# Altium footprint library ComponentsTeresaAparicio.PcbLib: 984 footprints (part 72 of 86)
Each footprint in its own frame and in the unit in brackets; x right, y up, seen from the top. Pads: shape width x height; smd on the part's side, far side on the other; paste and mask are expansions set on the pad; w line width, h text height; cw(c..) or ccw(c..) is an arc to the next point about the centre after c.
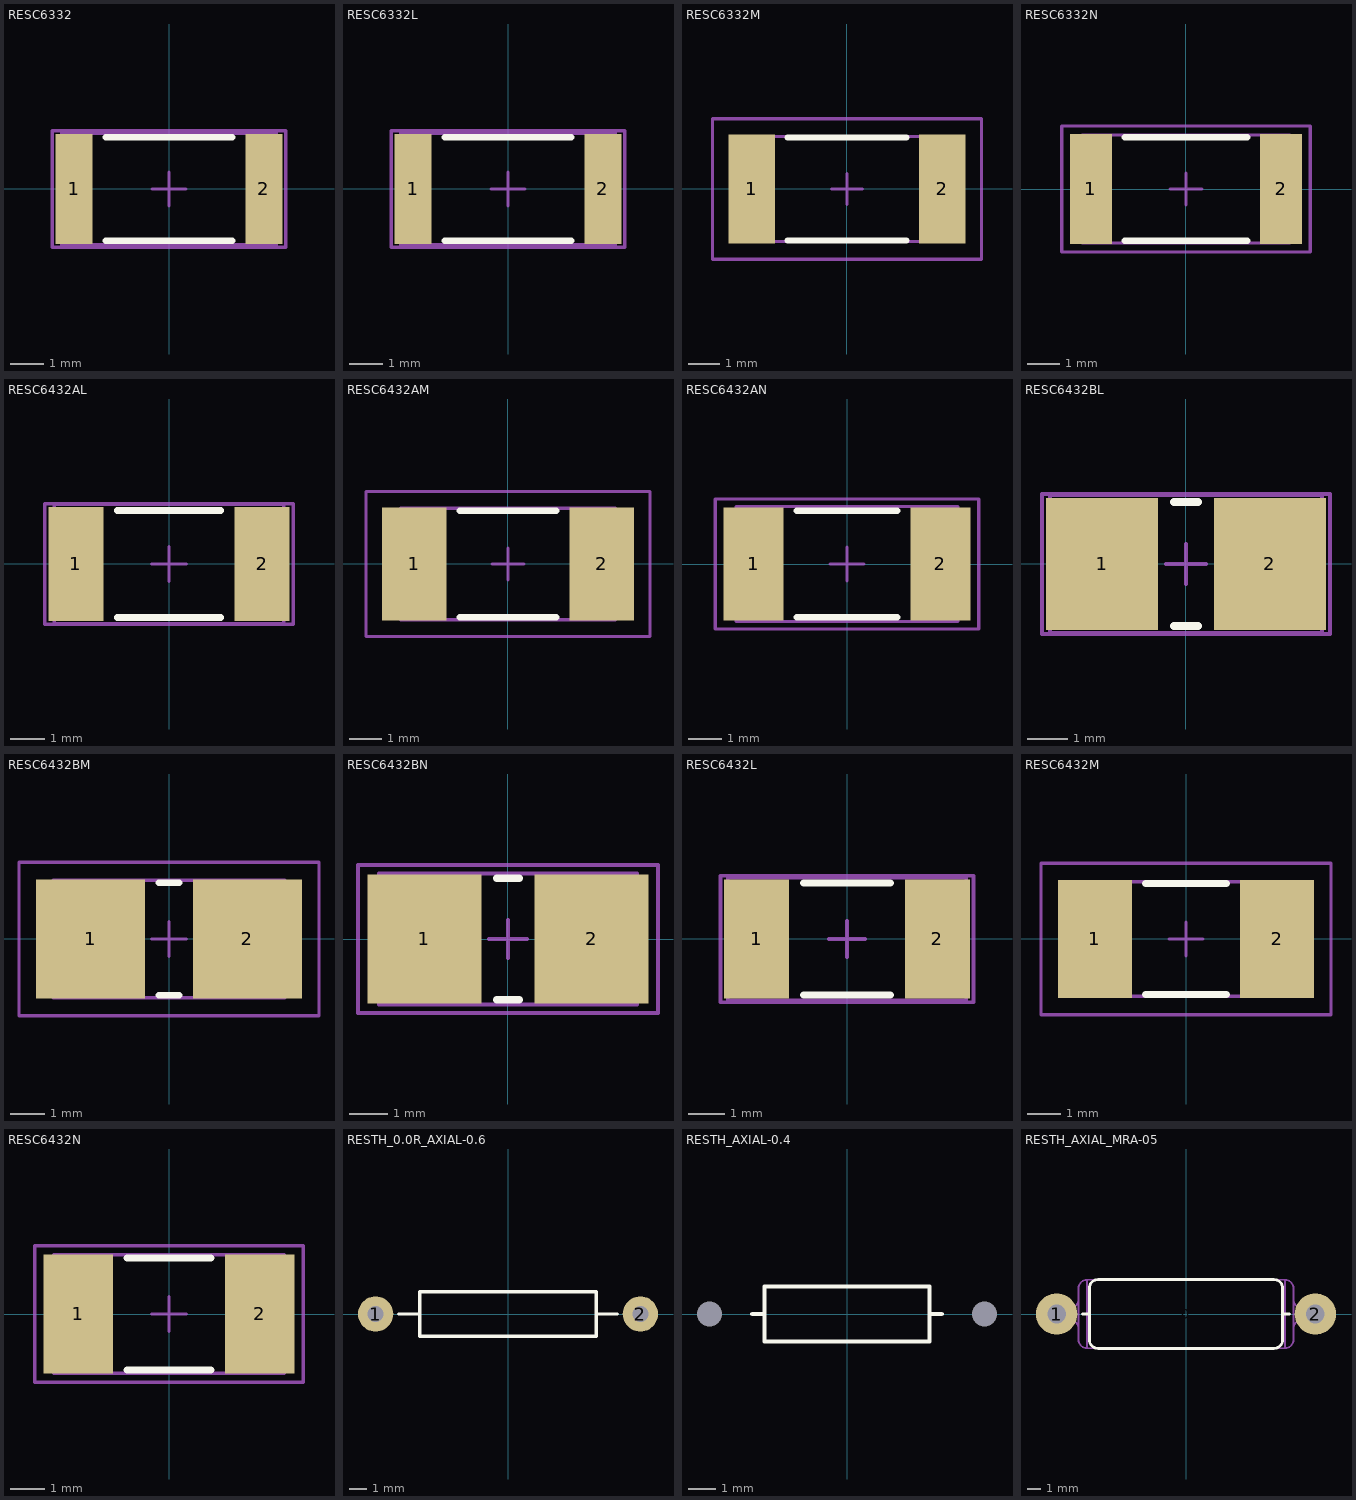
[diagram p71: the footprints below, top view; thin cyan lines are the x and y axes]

## RESC6332 [mm] "Chip Resistor, Body 6.3x3.2mm, IPC High Density"
height 0.9
pads (2):
  rect 1.1x3.3 smd: 1(-2.85,0) 2(2.85,0)
Top Overlay:
  lines w0.2: -1.9,-1.55 1.9,-1.55 ; -1.9,1.55 1.9,1.55
Mechanical 13:
  lines w0.1: -3.225,-1.675 -3.225,1.675 3.225,1.675 3.225,-1.675 -3.225,-1.675
Mechanical 15:
  lines w0.1: -0.5,0 0.5,0 ; 0,-0.5 0,0.5 ; -3.5,-1.75 -3.5,1.75 3.5,1.75 3.5,-1.75 -3.5,-1.75
3D body: height 0.9, standoff 0, extent -3.225,-1.675 3.225,1.675

## RESC6332L [mm] "Chip Resistor, Body 6.3x3.2mm, IPC High Density"
height 0.71
pads (2):
  rect 1.1x3.3 smd: 1(-2.85,0) 2(2.85,0)
Top Overlay:
  lines w0.2: -1.9,-1.55 1.9,-1.55 ; -1.9,1.55 1.9,1.55
Mechanical 13:
  lines w0.1: -3.225,-1.675 3.225,-1.675 3.225,1.675 -3.225,1.675 -3.225,-1.675
Mechanical 15:
  lines w0.1: -0.5,0 0.5,0 ; 0,-0.5 0,0.5 ; -3.5,-1.75 3.5,-1.75 3.5,1.75 -3.5,1.75 -3.5,-1.75
3D body: height 0.71, standoff 0, extent -3.225,-1.675 3.225,1.675

## RESC6332M [mm] "Chip Resistor, Body 6.3x3.2mm, IPC Low Density"
height 0.71
pads (2):
  rect 1.5x3.5 smd: 1(-3.05,0) 2(3.05,0)
Top Overlay:
  lines w0.2: -1.9,-1.65 1.9,-1.65 ; -1.9,1.65 1.9,1.65
Mechanical 13:
  lines w0.1: -3.225,-1.675 -3.225,1.675 3.225,1.675 3.225,-1.675 -3.225,-1.675
Mechanical 15:
  lines w0.1: -0.5,0 0.5,0 ; 0,-0.5 0,0.5 ; -4.3,-2.25 -4.3,2.25 4.3,2.25 4.3,-2.25 -4.3,-2.25
3D body: height 0.71, standoff 0, extent -3.225,-1.675 3.225,1.675

## RESC6332N [mm] "Chip Resistor, Body 6.3x3.2mm, IPC Medium Density"
height 0.71
pads (2):
  rect 1.3x3.4 smd: 1(-2.95,0) 2(2.95,0)
Top Overlay:
  lines w0.2: -1.9,-1.6 1.9,-1.6 ; -1.9,1.6 1.9,1.6
Mechanical 13:
  lines w0.1: -3.225,-1.675 3.225,-1.675 3.225,1.675 -3.225,1.675 -3.225,-1.675
Mechanical 15:
  lines w0.1: -0.5,0 0.5,0 ; 0,-0.5 0,0.5 ; -3.85,-1.95 3.85,-1.95 3.85,1.95 -3.85,1.95 -3.85,-1.95
3D body: height 0.71, standoff 0, extent -3.225,-1.675 3.225,1.675

## RESC6432AL [mm] "Chip Resistor, Body 6.4x3.2mm, IPC High Density"
height 1.1
pads (2):
  rect 1.6x3.3 smd: 1(-2.7,0) 2(2.7,0)
Top Overlay:
  lines w0.2: -1.5,-1.55 1.5,-1.55 ; -1.5,1.55 1.5,1.55
Mechanical 13:
  lines w0.1: -3.325,-1.725 3.325,-1.725 3.325,1.725 -3.325,1.725 -3.325,-1.725
Mechanical 15:
  lines w0.1: -0.5,0 0.5,0 ; 0,-0.5 0,0.5 ; -3.6,-1.75 3.6,-1.75 3.6,1.75 -3.6,1.75 -3.6,-1.75
3D body: height 1.1, standoff 0, extent -3.325,-1.725 3.325,1.725

## RESC6432AM [mm] "Chip Resistor, Body 6.4x3.2mm, IPC Low Density"
height 1.1
pads (2):
  rect 2x3.5 smd: 1(-2.9,0) 2(2.9,0)
Top Overlay:
  lines w0.2: -1.5,-1.65 1.5,-1.65 ; -1.5,1.65 1.5,1.65
Mechanical 13:
  lines w0.1: -3.325,-1.725 -3.325,1.725 3.325,1.725 3.325,-1.725 -3.325,-1.725
Mechanical 15:
  lines w0.1: -0.5,0 0.5,0 ; 0,-0.5 0,0.5 ; -4.4,-2.25 -4.4,2.25 4.4,2.25 4.4,-2.25 -4.4,-2.25
3D body: height 1.1, standoff 0, extent -3.325,-1.725 3.325,1.725

## RESC6432AN [mm] "Chip Resistor, Body 6.4x3.2mm, IPC Medium Density"
height 1.1
pads (2):
  rect 1.8x3.4 smd: 1(-2.8,0) 2(2.8,0)
Top Overlay:
  lines w0.2: -1.5,-1.6 1.5,-1.6 ; -1.5,1.6 1.5,1.6
Mechanical 13:
  lines w0.1: -3.325,-1.725 3.325,-1.725 3.325,1.725 -3.325,1.725 -3.325,-1.725
Mechanical 15:
  lines w0.1: -0.5,0 0.5,0 ; 0,-0.5 0,0.5 ; -3.95,-1.95 3.95,-1.95 3.95,1.95 -3.95,1.95 -3.95,-1.95
3D body: height 1.1, standoff 0, extent -3.325,-1.725 3.325,1.725

## RESC6432BL [mm] "Chip Resistor, Body 6.4x3.2mm, IPC High Density"
height 1.1
pads (2):
  rect 2.8x3.3 smd: 1(-2.1,0) 2(2.1,0)
Top Overlay:
  lines w0.2: -0.3,-1.55 0.3,-1.55 ; -0.3,1.55 0.3,1.55
Mechanical 13:
  lines w0.1: -3.4,-1.725 3.4,-1.725 3.4,1.725 -3.4,1.725 -3.4,-1.725
Mechanical 15:
  lines w0.1: -0.5,0 0.5,0 ; 0,-0.5 0,0.5 ; -3.6,-1.75 3.6,-1.75 3.6,1.75 -3.6,1.75 -3.6,-1.75
3D body: height 1.1, standoff 0, extent -3.4,-1.725 3.4,1.725

## RESC6432BM [mm] "Chip Resistor, Body 6.4x3.2mm, IPC Low Density"
height 1.1
pads (2):
  rect 3.2x3.5 smd: 1(-2.3,0) 2(2.3,0)
Top Overlay:
  lines w0.2: -0.3,-1.65 0.3,-1.65 ; -0.3,1.65 0.3,1.65
Mechanical 13:
  lines w0.1: -3.4,-1.725 3.4,-1.725 3.4,1.725 -3.4,1.725 -3.4,-1.725
Mechanical 15:
  lines w0.1: -0.5,0 0.5,0 ; 0,-0.5 0,0.5 ; -4.4,-2.25 4.4,-2.25 4.4,2.25 -4.4,2.25 -4.4,-2.25
3D body: height 1.1, standoff 0, extent -3.4,-1.725 3.4,1.725

## RESC6432BN [mm] "Chip Resistor, Body 6.4x3.2mm, IPC Medium Density"
height 1.1
pads (2):
  rect 3x3.4 smd: 1(-2.2,0) 2(2.2,0)
Top Overlay:
  lines w0.2: -0.3,-1.6 0.3,-1.6 ; -0.3,1.6 0.3,1.6
Mechanical 13:
  lines w0.1: -3.4,-1.725 3.4,-1.725 3.4,1.725 -3.4,1.725 -3.4,-1.725
Mechanical 15:
  lines w0.1: -0.5,0 0.5,0 ; 0,-0.5 0,0.5 ; -3.95,-1.95 3.95,-1.95 3.95,1.95 -3.95,1.95 -3.95,-1.95
3D body: height 1.1, standoff 0, extent -3.4,-1.725 3.4,1.725

## RESC6432L [mm] "Chip Resistor, Body 6.4x3.2mm, IPC High Density"
height 1.2
pads (2):
  rect 1.8x3.3 smd: 1(-2.5,0) 2(2.5,0)
Top Overlay:
  lines w0.2: -1.2,-1.55 1.2,-1.55 ; -1.2,1.55 1.2,1.55
Mechanical 13:
  lines w0.1: -3.3,-1.7 3.3,-1.7 3.3,1.7 -3.3,1.7 -3.3,-1.7
Mechanical 15:
  lines w0.1: -0.5,0 0.5,0 ; 0,-0.5 0,0.5 ; -3.5,-1.75 3.5,-1.75 3.5,1.75 -3.5,1.75 -3.5,-1.75
3D body: height 1.2, standoff 0, extent -3.3,-1.7 3.3,1.7

## RESC6432M [mm] "Chip Resistor, Body 6.4x3.2mm, IPC Low Density"
height 1.2
pads (2):
  rect 2.2x3.5 smd: 1(-2.7,0) 2(2.7,0)
Top Overlay:
  lines w0.2: -1.2,-1.65 1.2,-1.65 ; -1.2,1.65 1.2,1.65
Mechanical 13:
  lines w0.1: -3.3,-1.7 -3.3,1.7 3.3,1.7 3.3,-1.7 -3.3,-1.7
Mechanical 15:
  lines w0.1: -0.5,0 0.5,0 ; 0,-0.5 0,0.5 ; -4.3,-2.25 -4.3,2.25 4.3,2.25 4.3,-2.25 -4.3,-2.25
3D body: height 1.2, standoff 0, extent -3.3,-1.7 3.3,1.7

## RESC6432N [mm] "Chip Resistor, Body 6.4x3.2mm, IPC Medium Density"
height 1.2
pads (2):
  rect 2x3.4 smd: 1(-2.6,0) 2(2.6,0)
Top Overlay:
  lines w0.2: -1.2,-1.6 1.2,-1.6 ; -1.2,1.6 1.2,1.6
Mechanical 13:
  lines w0.1: -3.3,-1.7 -3.3,1.7 3.3,1.7 3.3,-1.7 -3.3,-1.7
Mechanical 15:
  lines w0.1: -0.5,0 0.5,0 ; 0,-0.5 0,0.5 ; -3.85,-1.95 -3.85,1.95 3.85,1.95 3.85,-1.95 -3.85,-1.95
3D body: height 1.2, standoff 0, extent -3.3,-1.7 3.3,1.7

## RESTH_0.0R_AXIAL-0.6 [mil] "Axial Resistor 0 Ohm, Thru-Hole; 2 Leads; 0.6 in Pin Spacing"
height 102.36
pads (2):
  round 80 hole 36: 1(-300,0) 2(300,0)
Top Overlay:
  lines w7.87: -248.03,0 -200,0 ; 200,0 248.03,0 ; -200,-50 200,-50 200,50 -200,50 -200,-50
3D body: height 102.76, standoff -98.43, extent -311.8,-51.57 311.82,51.58

## RESTH_AXIAL-0.4 [mil]
height 80
pads (2):
  round 0 / inner round 0 / far side round 100 hole 36 unplated: 1(-200,0) 2(200,0)
Top Overlay:
  lines w6: -137.8,0 -120,0 ; 120,0 137.8,0 ; -120,-40 -120,40 120,40 120,-40 -120,-40
3D body: height 102.23, standoff -100, extent -211.81,-50.27 211.81,50.27

## RESTH_AXIAL_MRA-05 [mil] "MRA-05 Axial Resistor Thru-Hole; 2 Leads"
height 198
pads (3):
  round 50 on Mech14: 0(0,0)
  round 120 hole 54: 1(-375,0) 2(375,0)
Top Overlay:
  lines w7.87: -300,0 -280,0 ; 280,0 300,0 ; -280,-75 ccw(c-255,-75) -255,-100 255,-100 ccw(c255,-75) 280,-75 280,75 ccw(c255,75) 255,100 -255,100 ccw(c-255,75) -280,75 -280,-75
Mechanical 13:
  lines w5: -337,-16.89 -337,17 ; -312,-42 ccw(c-337,-42) -337,-17 -375,-17 cw(c-375,0) -375,17 -337,17 ; -312,42 cw(c-337,42) -337,17 ; 312,-42 cw(c337,-42) 337,-17 ; 312,42 ccw(c337,42) 337,17 375,17 cw(c375,0) 375,-17 337,-17 ; 337,16.89 337,-17 ; -341,-17 -341,-16.98 ; -341,-16.98 -341,-16.52 -341,-15.46 -341,-13.85 -341,-11.73 -341,-9.19 -341,-6.32 -341,-3.22 -341,0 -341,3.22 -341,6.32 -341,9.19 -341,11.73 -341,13.85 -341,15.46 -341,16.52 -341,16.98 ; -341,16.98 -341,17 ; -287,-99 cw(c-287,-74) -312,-74 -312,74 cw(c-287,74) -287,99 ; -287,-99 287,-99 ; -287,-99 -287,99 ; -287,99 287,99 ; 287,-99 ccw(c287,-74) 312,-74 312,74 ccw(c287,74) 287,99 ; 287,-99 287,99 ; 341,-17 341,-16.98 ; 341,-16.98 341,-16.52 341,-15.46 341,-13.85 341,-11.73 341,-9.19 341,-6.32 341,-3.22 341,0 341,3.22 341,6.32 341,9.19 341,11.73 341,13.85 341,15.46 341,16.52 341,16.98 ; 341,16.98 341,17
3D body: height 197.22, standoff -100, extent -391.99,-98.8 392.01,98.81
